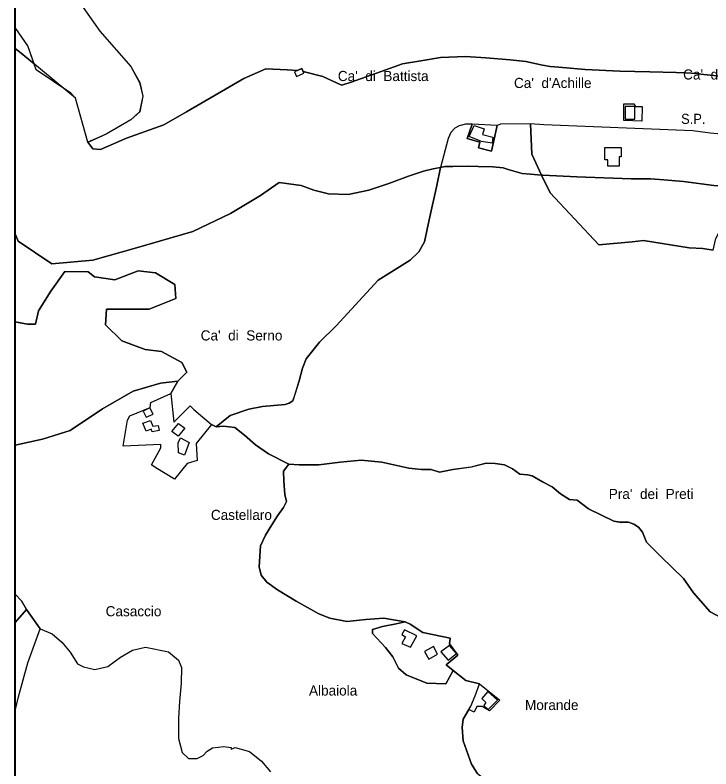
# Model space of a CAD drawing. Extents: x 652791 to 656927, y 889884 to 892405.
# Drawn here: x 654894 to 655580, y 891133 to 891877 of the extents above; entities that cross this region are included whole.
import ezdxf
from ezdxf.enums import TextEntityAlignment as Align

# ---------------------------------------------------------------- set-up
doc = ezdxf.new("R2010")
doc.units = 0
doc.header["$LTSCALE"] = 5.6
for name, color, linetype, lineweight in [('2', 7, 'Continuous', 25), ('3', 7, 'Continuous', 25), ('30', 7, 'Continuous', 25), ('35', 7, 'Continuous', 25), ('36', 7, 'Continuous', 25), ('37', 7, 'Continuous', 25), ('4', 7, 'Continuous', 25), ('55', 7, 'Continuous', 25), ('6', 7, 'Continuous', 25), ('61', 7, 'Continuous', 35)]:
    doc.layers.add(name, color=color, linetype=linetype, lineweight=lineweight)
doc.layers.add('60', color=7, linetype='Continuous')

msp = doc.modelspace()

# ---------------------------------------------------------------- linework, layer by layer
at = {"layer": '2'}
for points in [[(655346.72, 891767.62), (655356.68, 891764.44), (655355.16, 891758.9), (655365.26, 891756.27), (655364.57, 891750.32), (655353.92, 891751.85), (655342.02, 891756.69)], [(655259.29, 891252.74), (655266.61, 891243.36), (655272.1, 891232.14), (655279.87, 891225.51), (655300, 891217.5), (655318.75, 891216.81), (655326.07, 891229.86), (655319.21, 891235.35), (655330.87, 891244.96), (655322.41, 891256.18), (655323.1, 891261.67), (655296.11, 891267.39), (655283.76, 891275.63), (655278.73, 891277.92), (655270.04, 891275.86), (655256.32, 891273.34), (655246.49, 891270.37), (655246.49, 891266.47)], [(655278.11, 891270.03), (655275.42, 891265.54), (655279, 891263.15), (655275.42, 891256.57), (655284.18, 891252.86), (655290.3, 891264.21)], [(655314.08, 891248.17), (655321.11, 891240.01), (655329.26, 891246.56), (655322.5, 891254.71)], [(655297.86, 891248.78), (655302.08, 891241.21), (655310.66, 891246.03), (655306.74, 891253.58)]]:
    msp.add_lwpolyline(points, close=True, dxfattribs=at)
at = {"layer": '3'}
for points in [[(655037.79, 891452.77), (655000.69, 891451.15), (655005.07, 891477.01), (655007.07, 891481.17), (655027.18, 891489.43), (655027.95, 891494.33), (655047.54, 891503.35), (655050.51, 891474.93), (655066.89, 891491.09), (655070.31, 891487.58), (655087.84, 891472.58), (655072.62, 891453.88), (655073.54, 891437.03), (655063.62, 891434.03), (655051.4, 891418.61), (655032.72, 891429.92), (655028.57, 891432.92), (655037.79, 891449.54)], [(655020.25, 891485.75), (655023.31, 891479.73), (655030.12, 891482.68), (655026.94, 891489.04)], [(655019.96, 891473.95), (655027.44, 891476.5), (655029.78, 891471.09), (655035.25, 891471.56), (655036.08, 891466.63), (655029.17, 891465.48), (655028.35, 891468.03), (655023.33, 891466.13)], [(655048.58, 891465.8), (655055.16, 891473.46), (655061.32, 891468.93), (655054.87, 891461.21)], [(655054.82, 891454.45), (655057.13, 891459.39), (655065.88, 891454.96), (655061.11, 891442.24), (655055.21, 891444.74)]]:
    msp.add_lwpolyline(points, close=True, dxfattribs=at)
at = {"layer": '30'}
for points in [[(655624.23, 891707.41), (655638.75, 891716.34), (655643.58, 891729.3), (655649.69, 891749.91), (655649.69, 891749.91), (655654.92, 891765.7), (655659.31, 891774.47), (655662.32, 891779.79), (655651.25, 891774.53), (655631.73, 891761.54), (655620.08, 891756.78), (655611.93, 891756.78), (655601.23, 891757.96), (655579.7, 891760.18), (655562.48, 891762.4), (655415.63, 891768.33), (655402.54, 891769.12), (655403.75, 891739.36), (655413.39, 891718.75)], [(655413.39, 891718.75), (655414.72, 891718.64), (655448.2, 891717.07), (655501.55, 891714.9), (655520.78, 891714.9), (655533.84, 891714.12), (655553.45, 891712.46), (655583.07, 891708.37), (655608.33, 891707.35), (655621.67, 891706.86), (655624.23, 891707.41)], [(655624.23, 891707.41), (655621.67, 891706.86), (655608.33, 891707.35), (655583.07, 891708.37), (655553.45, 891712.46), (655533.84, 891714.12), (655520.78, 891714.9), (655501.55, 891714.9), (655448.2, 891717.07), (655414.72, 891718.64), (655413.39, 891718.75)], [(655413.39, 891718.75), (655421.64, 891701.11), (655469.89, 891649.98), (655502.53, 891652.82)], [(655502.53, 891652.82), (655513.97, 891654.03), (655558.88, 891647.07), (655572.43, 891646.12), (655582.42, 891644.49), (655585.17, 891656.03), (655602.35, 891688.57), (655616.37, 891702.58), (655624.23, 891707.41)]]:
    msp.add_lwpolyline(points, dxfattribs=at)
at = {"layer": '35'}
msp.add_line((655413.39, 891718.75), (655402.51, 891719.63), dxfattribs=at)
for points in [[(655332.2, 891767.4), (655327.83, 891765.06), (655323.76, 891760.85)], [(655344.78, 891769.09), (655338.31, 891768.88), (655332.2, 891767.4)], [(655402.54, 891769.12), (655372.88, 891769.05), (655369.38, 891767.53), (655366.07, 891751.07), (655364.09, 891742.17), (655351.2, 891745.67), (655352.51, 891751.29), (655339.9, 891754.79), (655344.78, 891769.09)], [(655365.21, 891726.83), (655375.48, 891725.71), (655380.51, 891724.2), (655394.07, 891720.32), (655402.51, 891719.63), (655413.39, 891718.75), (655403.75, 891739.36), (655402.54, 891769.12)], [(655323.76, 891760.85), (655321.18, 891754.91), (655313.68, 891726.31)], [(655313.68, 891726.31), (655309.86, 891708.34), (655302.53, 891674.41), (655297.92, 891652.75), (655292.31, 891643.02)], [(655313.68, 891726.31), (655317.92, 891727.16), (655325.85, 891727.35), (655341.68, 891727.63), (655350.84, 891727.32), (655365.21, 891726.83)], [(655350.84, 891727.32), (655341.68, 891727.63), (655325.85, 891727.35), (655317.92, 891727.16), (655313.68, 891726.31)], [(655402.51, 891719.63), (655394.07, 891720.32), (655380.51, 891724.2), (655375.48, 891725.71), (655365.21, 891726.83), (655350.84, 891727.32)], [(655582.42, 891644.49), (655572.43, 891646.12), (655558.88, 891647.07), (655513.97, 891654.03), (655502.53, 891652.82), (655469.89, 891649.98), (655421.64, 891701.11), (655413.39, 891718.75)], [(655292.31, 891643.02), (655283.75, 891634.73), (655252.01, 891614.96)], [(655252.01, 891614.96), (655210.59, 891570.1), (655194.14, 891553.82)], [(655194.14, 891553.82), (655181.19, 891537.53), (655177.52, 891528.25), (655174.19, 891515.81), (655168, 891496.14), (655164.37, 891493.8), (655160.28, 891492.34), (655138.16, 891490.28), (655124.57, 891487.75), (655106.22, 891481.52), (655092.46, 891470.37)], [(655092.46, 891470.37), (655099.7, 891471.12), (655110.72, 891469.6), (655120.21, 891462), (655131.23, 891452.49), (655144.15, 891443.75), (655164.06, 891433.48), (655174.16, 891432.73), (655193.53, 891432.73), (655214.8, 891435.39), (655235.32, 891437.29), (655255.83, 891435.39), (655282.42, 891429.69), (655294.96, 891428.17), (655304.46, 891428.17), (655312.81, 891425.5), (655325.73, 891428.17), (655344.34, 891430.83), (655358.55, 891434.64), (655367.52, 891434.25), (655376.63, 891432.72), (655384.78, 891428.82), (655391.83, 891423.6), (655399.53, 891423), (655404.18, 891421.83), (655414.12, 891415.93)], [(655414.12, 891415.93), (655423.89, 891411.2), (655432.12, 891404.21), (655440.89, 891398.78), (655448.41, 891398), (655459.68, 891389.38)], [(655459.68, 891389.38), (655484.52, 891377.35), (655491.97, 891376.1), (655499.16, 891376.26), (655504.28, 891374.24)], [(655504.28, 891374.24), (655508.86, 891371.37), (655512.89, 891366.48), (655516.69, 891356.69), (655531.34, 891342.01), (655553.3, 891320.75)], [(655553.3, 891320.75), (655563.31, 891306.62), (655579.68, 891287.83)], [(655579.68, 891287.83), (655595.82, 891279.36), (655609.62, 891270.6)]]:
    msp.add_lwpolyline(points, dxfattribs=at)
msp.add_lwpolyline([(654894.04, 891277.42), (654894.04, 891190.08), (654897.5, 891203.98), (654906.78, 891237.49), (654918.63, 891270.99), (654905.34, 891290.03)], close=True, dxfattribs=at)
at = {"layer": '36'}
for points in [[(654894.04, 891863.87), (654894.04, 892404.69), (654981.23, 892404.69), (654981.62, 892400.32), (654974.54, 892395.59), (654970.6, 892390.08), (654981.62, 892368.8), (654993.43, 892377.47), (654996.58, 892386.92), (655002.88, 892386.92), (655003.66, 892377.47), (654994.22, 892363.28), (654983.2, 892349.89), (654983.99, 892335.7), (654997.37, 892326.25), (655008.39, 892317.58), (655017.05, 892301.82), (655028.85, 892293.94), (655048.53, 892290.78), (655065.85, 892295.51), (655080.8, 892286.84), (655086.31, 892278.17), (655113.08, 892276.6)], [(654961.23, 891884.22), (654977.73, 891860.71), (655008.15, 891825.7), (655016.91, 891810.19), (655020.01, 891796.69), (655016.91, 891781.18), (655008.15, 891773.18), (654983.91, 891759.17), (654965.86, 891750.97), (654965.82, 891751.05)], [(654965.82, 891751.05), (654953.74, 891794.55), (654949.09, 891799.5), (654914.7, 891822.56), (654906.58, 891846.2), (654894.72, 891863.21), (654894.04, 891863.87)], [(654894.04, 891013.14), (654894.04, 891190.08), (654897.5, 891203.98), (654906.78, 891237.49), (654918.63, 891270.99), (654930.49, 891265.99), (654940.28, 891257.99), (654948.53, 891247.99), (654955.75, 891236.49), (654961.42, 891233.49), (654972.76, 891230.99), (654985.64, 891233.99), (654998.02, 891242.99), (655009.87, 891249.99), (655022.76, 891252.99), (655045.44, 891248.49), (655055.23, 891239.99), (655058.33, 891232.99), (655057.81, 891217.49), (655056.26, 891199.48), (655055.23, 891182.98)], [(655055.23, 891182.98), (655055.23, 891162.98), (655058.84, 891148.98), (655065.03, 891142.98), (655073.79, 891142.98), (655079.46, 891145.98), (655083.58, 891150.48), (655088.74, 891153.48), (655100.08, 891154.98), (655107.2, 891153.87), (655107.24, 891152.46), (655111.19, 891153.99), (655125.22, 891149.86), (655137.08, 891140.36), (655145.84, 891129.86)]]:
    msp.add_lwpolyline(points, dxfattribs=at)
for points in [[(654894.04, 891573.95), (654894.04, 891452.35), (654921.18, 891458.05), (654948.24, 891466.8), (654980.3, 891488.18), (655010.36, 891505.68), (655037.42, 891513.46), (655054.45, 891515.4), (655063.47, 891524.15), (655058.46, 891533.87), (655038.42, 891544.56), (655022.39, 891546.51), (654999.34, 891555.26), (654983.31, 891570.81), (654984.31, 891586.36), (655000.34, 891586.36), (655026.4, 891586.36), (655052.45, 891597.06), (655051.45, 891610.67), (655032.41, 891622.33), (655015.37, 891624.28), (654992.33, 891615.53), (654972.29, 891618.44), (654966.27, 891623.3), (654943.25, 891623.69), (654929.22, 891604.24), (654917.2, 891584.8), (654914.17, 891571.78), (654906.15, 891571.78)], [(654894.04, 891305.15), (654894.04, 891277.42), (654905.34, 891290.03), (654900.33, 891298.77)]]:
    msp.add_lwpolyline(points, close=True, dxfattribs=at)
at = {"layer": '37'}
for p, q in [((655047.54, 891503.35), (655054.45, 891515.4)), ((655087.84, 891472.58), (655092.46, 891470.37)), ((655152.78, 891309.37), (655142.42, 891316.97)), ((655239.85, 891280.32), (655221.19, 891278.25)), ((655055.24, 891239.99), (655058.34, 891232.99)), ((655300.01, 891217.5), (655279.88, 891225.51)), ((655056.27, 891199.48), (655055.24, 891182.98)), ((655058.85, 891148.98), (655065.04, 891142.98)), ((655137.08, 891140.36), (655145.84, 891129.86))]:
    msp.add_line(p, q, dxfattribs=at)
for points in [[(654961.24, 891884.22), (654977.74, 891860.71), (655008.16, 891825.7), (655016.92, 891810.19), (655020.02, 891796.69), (655016.92, 891781.18), (655008.16, 891773.18), (654983.92, 891759.17), (654965.82, 891751.05)], [(655430.37, 891825.09), (655456.38, 891823.01), (655490.4, 891821.27), (655520.05, 891820.67), (655546.19, 891820.04), (655561.35, 891819.34), (655579.49, 891817.36), (655597.12, 891815.5), (655608.99, 891814.04), (655625.11, 891824.07), (655640.55, 891833.67), (655658.39, 891840.35), (655677.77, 891844.48), (655692.81, 891846.73), (655700.24, 891847.42)], [(655211.7, 891809.51), (655216.33, 891807.57), (655217.29, 891807.64), (655225.68, 891810.38), (655259.64, 891822.71), (655276.25, 891828.39), (655294.18, 891831.5), (655313.72, 891834.83), (655338.39, 891835.61), (655358.19, 891834.55), (655382.34, 891832.59), (655397.87, 891830.69), (655414.28, 891827.27), (655421.79, 891825.76), (655430.37, 891825.09)], [(655119.5, 891813.85), (655141.49, 891823.51), (655162.45, 891822.71), (655172.61, 891822.04), (655176.92, 891823.92), (655178.26, 891820.85), (655197.61, 891815.96), (655211.7, 891809.51)], [(654965.82, 891751.05), (654970.61, 891744.47), (654978.38, 891743.87), (655004.09, 891755.22), (655040.83, 891768.15), (655063.22, 891781.05), (655119.5, 891813.85)], [(655313.68, 891726.31), (655306.52, 891724.88), (655296.98, 891722.55), (655282.1, 891717.68), (655262.64, 891710.49), (655243.09, 891703.85), (655222.58, 891699.52), (655203.07, 891700.27), (655188.79, 891704), (655176.07, 891708.49), (655154.59, 891711.51)], [(655297.92, 891652.75), (655302.53, 891674.41), (655309.86, 891708.34), (655313.68, 891726.31)], [(655154.59, 891711.51), (655136.15, 891698.51), (655106.58, 891680.76), (655069.38, 891663.08), (655013.73, 891647.04), (654970.69, 891634.74), (654930.42, 891631.24), (654897.08, 891653.48), (654896.99, 891653.68), (654894.04, 891660.74)], [(654894.04, 891660.74), (654894.04, 891573.95), (654897.08, 891573.41), (654897.08, 891573.37), (654906.15, 891571.78), (654914.17, 891571.78), (654917.21, 891584.8), (654929.23, 891604.24), (654943.26, 891623.69), (654966.27, 891623.3), (654972.29, 891618.44), (654992.33, 891615.53), (655015.37, 891624.28), (655032.41, 891622.33), (655051.45, 891610.67), (655052.45, 891597.06), (655026.4, 891586.36), (655000.34, 891586.36), (654984.31, 891586.36), (654983.31, 891570.81), (654999.34, 891555.26), (655022.39, 891546.51), (655038.42, 891544.56), (655058.46, 891533.87), (655063.47, 891524.15), (655054.45, 891515.4), (655047.54, 891503.35), (655050.51, 891474.93), (655066.89, 891491.09), (655070.31, 891487.58), (655087.84, 891472.58), (655092.46, 891470.37), (655106.22, 891481.52), (655124.57, 891487.75)], [(655283.75, 891634.73), (655292.31, 891643.02), (655297.92, 891652.75)], [(655194.14, 891553.82), (655210.59, 891570.1), (655252.01, 891614.96), (655283.75, 891634.73)], [(655174.19, 891515.81), (655177.52, 891528.25), (655181.19, 891537.53), (655194.14, 891553.82)], [(655144.15, 891443.75), (655131.23, 891452.49), (655120.21, 891462), (655110.72, 891469.6), (655099.7, 891471.12), (655092.46, 891470.37), (655087.84, 891472.58), (655072.62, 891453.88), (655073.54, 891437.03), (655063.62, 891434.03), (655051.4, 891418.61), (655032.72, 891429.92), (655028.57, 891432.92), (655037.79, 891449.54), (655037.79, 891452.77), (655000.69, 891451.15), (655005.07, 891477.01), (655007.07, 891481.17), (655027.18, 891489.43), (655027.95, 891494.33), (655047.54, 891503.35), (655054.45, 891515.4), (655037.42, 891513.46), (655010.36, 891505.68), (654980.3, 891488.18), (654948.24, 891466.8), (654921.18, 891458.05), (654894.04, 891452.35)], [(655160.28, 891492.34), (655164.37, 891493.8), (655168, 891496.14), (655169.89, 891501.72), (655174.19, 891515.81)], [(655124.57, 891487.75), (655138.16, 891490.28), (655160.28, 891492.34)], [(654894.04, 891452.35), (654894.04, 891305.15), (654900.33, 891298.77), (654905.34, 891290.03), (654918.64, 891270.99)], [(655161.58, 891396.56), (655159.98, 891403.66), (655159.27, 891416.79), (655158.92, 891426.56), (655164.07, 891433.48), (655144.15, 891443.75)], [(655164.06, 891433.48), (655158.92, 891426.56), (655159.27, 891416.79), (655159.98, 891403.66), (655161.58, 891396.56), (655158.92, 891390.88), (655152.78, 891382.66), (655147.26, 891373.67), (655141.04, 891363.3), (655136.19, 891352.92), (655134.81, 891332.18), (655136.88, 891323.88), (655142.41, 891316.97), (655152.78, 891309.36), (655171.44, 891298.3), (655193.55, 891285.85), (655204.61, 891281.71), (655221.19, 891278.25), (655239.85, 891280.32), (655257.81, 891281.71), (655278.73, 891277.92), (655283.76, 891275.63), (655296.11, 891267.39), (655323.1, 891261.67), (655322.41, 891256.18), (655330.87, 891244.96), (655319.21, 891235.35), (655326.07, 891229.86)], [(655391.83, 891423.6), (655384.78, 891428.82), (655376.63, 891432.72), (655367.52, 891434.25), (655358.55, 891434.64), (655343.5, 891430.6), (655325.73, 891428.16), (655312.81, 891425.5), (655304.45, 891428.16), (655294.96, 891428.17), (655282.42, 891429.69), (655255.83, 891435.38), (655235.31, 891437.28), (655214.8, 891435.38), (655193.53, 891432.72), (655174.15, 891432.72), (655164.06, 891433.48)], [(655414.12, 891415.93), (655404.18, 891421.83), (655399.53, 891423), (655391.83, 891423.6)], [(655448.41, 891398), (655440.89, 891398.78), (655432.12, 891404.21), (655423.89, 891411.2), (655414.12, 891415.93)], [(655141.04, 891363.3), (655147.26, 891373.67), (655152.79, 891382.66), (655158.92, 891390.88), (655161.58, 891396.56)], [(655491.32, 891376.42), (655484.52, 891377.35), (655459.68, 891389.38), (655448.41, 891398)], [(655504.28, 891374.24), (655499.16, 891376.26), (655491.32, 891376.42)], [(655531.34, 891342.01), (655525.92, 891347.38), (655516.69, 891356.69), (655512.89, 891366.48), (655508.86, 891371.37), (655504.28, 891374.24)], [(655142.41, 891316.97), (655136.88, 891323.88), (655134.81, 891332.18), (655136.19, 891352.92), (655141.04, 891363.3)], [(655579.68, 891287.83), (655563.31, 891306.62), (655553.3, 891320.75), (655531.34, 891342.01)], [(655193.55, 891285.85), (655171.44, 891298.3), (655152.78, 891309.36)], [(655221.19, 891278.25), (655204.61, 891281.71), (655193.55, 891285.86)], [(655609.62, 891270.6), (655595.82, 891279.36), (655579.68, 891287.83)], [(655270.05, 891275.86), (655278.72, 891277.92), (655257.82, 891281.71), (655239.85, 891280.33)], [(654918.63, 891270.99), (654930.49, 891265.99), (654940.28, 891257.99), (654948.53, 891247.99), (654955.75, 891236.49), (654961.42, 891233.49), (654972.76, 891230.99), (654985.64, 891233.99), (654998.02, 891242.99), (655009.87, 891249.99), (655022.76, 891252.99), (655045.44, 891248.49), (655055.23, 891239.99)], [(655259.3, 891252.74), (655246.5, 891266.47), (655246.5, 891270.37), (655256.32, 891273.34), (655270.04, 891275.86)], [(655279.87, 891225.51), (655272.1, 891232.14), (655266.61, 891243.36), (655259.29, 891252.74)], [(655058.33, 891232.99), (655057.81, 891217.49), (655056.26, 891199.48)], [(655338.47, 891220.11), (655326.07, 891229.86), (655318.75, 891216.81), (655300, 891217.5)], [(655326.07, 891229.86), (655338.47, 891220.11), (655351.99, 891216.87), (655372.17, 891200.77), (655361.89, 891190.13), (655354.57, 891194.25), (655349.54, 891194.25), (655346.89, 891188.94), (655341.73, 891191.31), (655336.12, 891181.8), (655334.94, 891173.54), (655336.12, 891160.58), (655344.36, 891137.59), (655349.67, 891128.75), (655363.8, 891116.96), (655409.75, 891081.01), (655446.27, 891055.66), (655452.99, 891050.47)], [(655341.74, 891191.31), (655343.54, 891194.79), (655347.76, 891205.05), (655352, 891216.87), (655338.48, 891220.11)], [(655334.94, 891173.55), (655336.12, 891181.8), (655341.73, 891191.31)], [(655055.23, 891182.98), (655055.23, 891162.98), (655058.84, 891148.98)], [(655349.67, 891128.75), (655344.37, 891137.59), (655336.12, 891160.58), (655334.94, 891173.54)], [(655065.03, 891142.98), (655073.79, 891142.98), (655079.46, 891145.98), (655083.58, 891150.48), (655088.74, 891153.48), (655100.08, 891154.98), (655107.2, 891153.87), (655107.24, 891152.46)], [(655107.25, 891152.46), (655111.2, 891153.99), (655125.23, 891149.86), (655137.09, 891140.36)]]:
    msp.add_lwpolyline(points, dxfattribs=at)
msp.add_lwpolyline([(654894.04, 891863.87), (654894.04, 891843.68), (654899.93, 891838.93), (654912.7, 891828.4), (654906.58, 891846.2), (654894.72, 891863.21)], close=True, dxfattribs=at)
at = {"layer": '4'}
for points in [[(655494.52, 891772.43), (655494.52, 891788.95), (655504.43, 891788.95), (655505.98, 891786.52), (655512.42, 891786.33), (655512.22, 891771.93)], [(655495.72, 891786.41), (655495.72, 891773.93), (655505.28, 891773.77), (655505.28, 891786.41)], [(655369.38, 891767.53), (655344.78, 891769.09), (655339.9, 891754.79), (655352.51, 891751.29), (655351.2, 891745.67), (655364.09, 891742.17), (655366.07, 891751.07)], [(655347.75, 891205.05), (655351.99, 891216.87), (655372.17, 891200.77), (655361.89, 891190.13), (655354.57, 891194.25), (655349.54, 891194.25), (655346.89, 891188.94), (655341.73, 891191.31), (655343.53, 891194.79)], [(655360.3, 891209.06), (655354.33, 891202.24), (655358.4, 891198.25), (655356.34, 891195.46), (655360.75, 891191.58), (655369.7, 891200.58)]]:
    msp.add_lwpolyline(points, close=True, dxfattribs=at)
at = {"layer": '55'}
for points in [[(655119.5, 891813.85), (655063.22, 891781.05), (655040.83, 891768.15), (655004.09, 891755.22), (654978.38, 891743.87), (654970.61, 891744.47), (654965.82, 891751.05), (654953.74, 891794.55), (654899.93, 891838.93), (654894.04, 891843.68), (654894.04, 891660.74), (654897.07, 891653.47)], [(655756.37, 891845.22), (655751.28, 891846.27), (655731.29, 891848.24), (655713.48, 891848.65), (655692.81, 891846.73), (655677.77, 891844.48), (655658.39, 891840.35), (655640.55, 891833.67), (655625.11, 891824.07), (655608.99, 891814.04), (655597.12, 891815.5), (655579.49, 891817.36), (655561.35, 891819.34), (655546.19, 891820.04), (655520.05, 891820.67), (655490.4, 891821.27), (655456.38, 891823.01), (655430.37, 891825.09)], [(655430.37, 891825.09), (655421.79, 891825.76), (655414.28, 891827.27), (655397.87, 891830.69), (655382.34, 891832.59), (655358.19, 891834.55), (655338.39, 891835.61), (655313.72, 891834.83), (655294.18, 891831.5), (655276.25, 891828.39), (655259.64, 891822.71), (655225.68, 891810.38), (655217.29, 891807.64), (655216.33, 891807.57), (655211.7, 891809.51), (655197.61, 891815.96), (655178.26, 891820.85), (655176.92, 891823.92), (655172.61, 891822.04), (655162.45, 891822.71), (655141.49, 891823.51), (655119.5, 891813.85)], [(655136.14, 891698.5), (655154.59, 891711.51), (655176.07, 891708.49), (655188.79, 891704), (655203.07, 891700.27), (655222.58, 891699.52), (655243.09, 891703.84), (655262.64, 891710.48), (655282.1, 891717.67), (655296.97, 891722.55), (655306.51, 891724.88), (655317.92, 891727.16), (655325.85, 891727.35), (655341.68, 891727.63), (655350.84, 891727.32)], [(655350.84, 891727.32), (655365.21, 891726.83), (655375.48, 891725.71), (655380.51, 891724.2), (655394.07, 891720.32), (655402.51, 891719.63)], [(655402.51, 891719.63), (655414.72, 891718.64), (655448.2, 891717.07), (655501.55, 891714.9), (655520.78, 891714.9), (655533.84, 891714.12), (655553.45, 891712.46), (655583.07, 891708.37), (655608.33, 891707.35), (655621.67, 891706.86), (655641.05, 891711.03), (655650.1, 891714.15), (655660.98, 891720.45), (655669.78, 891726.16)], [(655013.72, 891647.04), (655069.38, 891663.07), (655106.58, 891680.75), (655136.14, 891698.5)], [(654897.07, 891653.47), (654930.41, 891631.23), (654970.69, 891634.74), (655013.72, 891647.04)]]:
    msp.add_lwpolyline(points, dxfattribs=at)
at = {"layer": '6'}
for points in [[(655176.92, 891823.92), (655169.59, 891820.73), (655171.59, 891816.14), (655178.92, 891819.34)], [(655489.73, 891727.67), (655478.63, 891727.67), (655478.63, 891733.87), (655475.63, 891733.87), (655475.63, 891745.87), (655491.73, 891745.87), (655491.73, 891736.87), (655489.73, 891736.87)]]:
    msp.add_lwpolyline(points, close=True, dxfattribs=at)
at = {"layer": '61', "lineweight": 40}
msp.add_lwpolyline([(654894.04, 892404.68), (656926.84, 892404.68), (656926.84, 889884.41), (654894.04, 889884.41)], close=True, dxfattribs=at)

# ---------------------------------------------------------------- texts
at = {"layer": '60'}
for s, p in [("Ca'  di  Battista", (655257.12, 891811.48)), ("Ca'  di  Bettini", (655593.97, 891813)), ("Ca'  d'Achille", (655424.36, 891804.61)), ("Ca'  di  Serno", (655117.42, 891555.53)), ("Pra'  dei  Preti", (655521.38, 891399.14)), ('Castellaro', (655117.27, 891378.45)), ('Casaccio', (655010.87, 891283.4)), ('Albaiola', (655207.72, 891205.2)), ('Morande', (655423.36, 891190.88))]:
    msp.add_text(s, height=10, dxfattribs=at).set_placement(p, align=Align.CENTER)
at = {"layer": '60', "width": 0.95}
msp.add_text('S.P.', height=10, dxfattribs=at).set_placement((655562.94, 891769.17), align=Align.CENTER)

doc.saveas('drawing.dxf')
